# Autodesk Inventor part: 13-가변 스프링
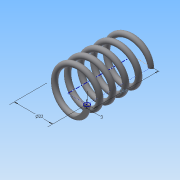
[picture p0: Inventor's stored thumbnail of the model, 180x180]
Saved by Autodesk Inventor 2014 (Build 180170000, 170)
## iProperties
Created: 2015-09
Part Number: 13-가변 스프링
Material: 강철, 탄소
Document SubType Name: Modeling
Designer: study
Density: 1 g/cm^3
Appearance: 반연마
Mass: 2.36745 g
Surface Area: 32.4192 cm^2
Volume: 2.36745 cm^3
Author: study
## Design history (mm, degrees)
sketch "스케치1"
  geometry: L1 (0, 0)-(11, 0); L2 (11, 0)-(11, 25.358); L3 (11, 25.358)-(0, 25.358); L4 (0, 25.358)-(0, 0); C1 r 1.5 at (11, 0)
  constraints: 8 end point, 2 parallel, 1 centre point, 1 coincident, 1 horizontal, 1 perpendicular
  dimensions: "d0" = 22 diameter of L2 L4; "d1" = 25.35829 distance of L1.end L2.end (derived); "d2" = 3 diameter of C1
feature "코일1" sketch "스케치1" pitch "d3" = 10; turns "d5" = 5; dims "d4" = 25.35829 (= d1), "d6" = 0, angle "d7" = 90 deg, angle "d8" = 90 deg, "d9" = 0, "d10" = 0
node "작업 평면1"
sketch "스케치2"
  geometry: L1 (-12.5, 0)-(-9.5, 0) reference; 1 further point
  constraints: 1 horizontal alignment
extrude "돌출1" cut sketch "스케치2" stored distance "d12" = 10; taper "d13" = 0 deg
node "작업 평면2"
sketch "스케치3"
  geometry: L1 (-9.5, 0)-(-12.5, 0) reference; 1 further point
  constraints: 1 horizontal alignment
extrude "돌출2" cut sketch "스케치3" stored distance "d15" = 10; taper "d16" = 0 deg
node "솔리드1"
node "절단 모서리 투영1"
node "절단 모서리 투영2"
other parameters: "d11" = 0, "d14" = 25.35829 (= d1)
